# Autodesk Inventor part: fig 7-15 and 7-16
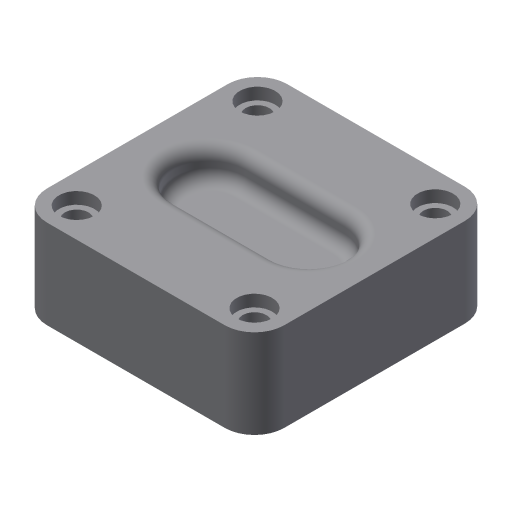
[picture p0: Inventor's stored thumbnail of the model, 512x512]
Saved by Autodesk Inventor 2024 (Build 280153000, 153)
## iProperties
Shininess: 77.0
Angle Display Precision: 2
Document Length Units: 11269
Document Angle Units: 11279
Document Time Units: 11290
Document Mass Units: 11283
Document Length Units Precision: 3
Document Angle Units Precision: 2
Created: 2001-12
Part Number: fig 7-15 and 7-16
Document SubType Name: Modeling
Designer: Renu Muthoo
Density: 1 g/cm^3
Material: Generic
Appearance: Default
Density: 0.0
Volumn: 0.0
Area: 0.0
PropertySet Name: Model Information
Control State: 0
Master: False
Checked Out: False
Author: Renu Muthoo
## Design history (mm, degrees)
sketch "Sketch1"
  geometry: L1 (-20, 20)-(20, 20); L2 (20, 20)-(20, -20.5); L3 (20, -20.5)-(-20, -20.5); L4 (-20, -20.5)-(-20, 20); 1 further point
  constraints: 8 end point, 2 parallel, 1 horizontal, 1 perpendicular, 1 other
  dimensions: "d0" = 40 distance of L1.start L1.end; "d1" = 40.5 distance of L3.end L1.start; "d100" = 20 distance from line of L4 point (0, 0); "d101" = 20 distance from line of L1 point (0, 0)
extrude "Extrusion1" new body sketch "Sketch1" distance "d2" = 15; taper "d3" = 0 deg
workplane "Work Plane1"
workplane "Work Plane2"
workplane "Work Plane3"
workplane "Work Plane4"
fillet "Fillet1" dims "d32" = 5
hole "Hole3" diameter "d66" = 4; stored, may be unused: countersink angle "d70" = 90 deg, drill point angle "d72" = 118 deg; dims "d64" = 10, "d65" = 10, "d67" = 6, "d68" = 6, "d69" = 2, "d71" = 8
hole "Hole4" diameter "d75" = 4; stored, may be unused: countersink angle "d79" = 90 deg, drill point angle "d81" = 118 deg; dims "d73" = 10, "d74" = 10, "d76" = 6, "d77" = 6, "d78" = 2, "d80" = 8
hole "Hole5" diameter "d84" = 4; stored, may be unused: countersink angle "d88" = 90 deg, drill point angle "d90" = 118 deg; dims "d82" = 10, "d83" = 10, "d85" = 6, "d86" = 6, "d87" = 2, "d89" = 8
hole "Hole6" diameter "d93" = 4; stored, may be unused: countersink angle "d97" = 90 deg, drill point angle "d99" = 118 deg; dims "d91" = 10, "d92" = 10, "d94" = 6, "d95" = 6, "d96" = 2, "d98" = 8
fillet "Fillet2" dims "d61" = 2
body "Solid1"
sketch "Sketch8"
  geometry: L1 (-9.844, 1.64)-(1.983, -10.187); L2 (10.469, -1.701)-(-1.358, 10.126); A1 r 6 centre (-5.601, 5.883) between (-1.358, 10.126) and (-9.844, 1.64); A2 r 6 centre (6.226, -5.944) between (1.983, -10.187) and (10.469, -1.701)
  constraints: 4 end point, 4 point on circle, 4 tangent, 2 centre point, 1 parallel
  dimensions: "d29" = 6 radius of A2
extrude "Extrusion2" cut sketch "Sketch8" distance "d30" = 5; taper "d31" = 0 deg
